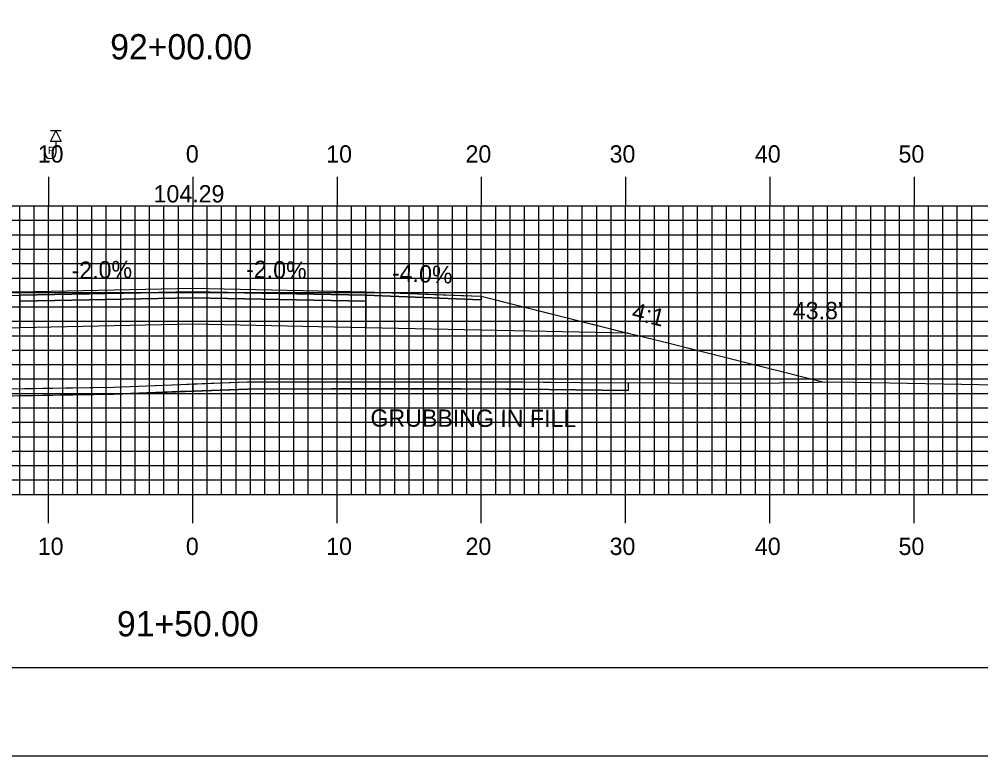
# Model space of a CAD drawing. Extents: x 1764939 to 1765282, y 442591 to 442811.
# Drawn here: x 1765092.8 to 1765159.5, y 442590.5 to 442641.6 of the extents above; entities that cross this region are included whole.
import ezdxf

# ---------------------------------------------------------------- set-up
doc = ezdxf.new("R2010")
doc.units = 0
for name, color, linetype in [('ANNOTATION', 7, 'Continuous'), ('BORDER', 7, 'Continuous'), ('D_Roadway_Centerline', 7, 'Continuous'), ('D_Roadway_Centerline_Text', 7, 'Continuous'), ('D_Roadway_Edge_Shoulder', 7, 'Continuous'), ('D_Roadway_Edge_TW', 7, 'Continuous'), ('D_Roadway_Pavement', 7, 'Continuous'), ('D_Roadway_SlopeLines', 7, 'Continuous'), ('D_Roadway_SubGrade', 7, 'Continuous'), ('D_Text_Standard', 7, 'Continuous'), ('GRUBBING IN FILL', 7, 'Continuous'), ('H_V ANNOTATION', 7, 'Continuous'), ('MAJOR', 7, 'Continuous'), ('MINOR', 7, 'Continuous'), ('PLOT BOUNDARY', 7, 'Continuous'), ('ROCKS', 7, 'Continuous'), ('S_Roadway_Centerline', 7, 'Continuous')]:
    doc.layers.add(name, color=color, linetype=linetype)

msp = doc.modelspace()

# ---------------------------------------------------------------- linework, layer by layer
at = {"layer": 'BORDER'}
msp.add_lwpolyline([(1764955.258, 442596.665), (1765275.258, 442596.665), (1765275.258, 442806.665), (1764955.258, 442806.665)], close=True, dxfattribs=at)
at = {"layer": 'D_Roadway_Centerline'}
msp.add_lwpolyline([(1765056.16, 442615.221), (1765056.164, 442615.222), (1765074.684, 442619.852), (1765074.686, 442619.853), (1765079.216, 442620.986), (1765084.858, 442622.396), (1765084.861, 442622.396), (1765088.541, 442622.544), (1765092.858, 442622.716), (1765092.862, 442622.716), (1765104.858, 442622.956), (1765104.863, 442622.956), (1765116.858, 442622.716), (1765116.862, 442622.716), (1765122.811, 442622.478), (1765124.857, 442622.396), (1765124.858, 442622.396), (1765135.028, 442619.853), (1765135.032, 442619.852), (1765136.858, 442619.396), (1765136.86, 442619.396), (1765148.626, 442616.453)], dxfattribs=at)
at = {"layer": 'D_Roadway_Edge_Shoulder'}
for points in [[(1765092.858, 442622.716), (1765084.858, 442622.396), (1765084.858, 442622.146), (1765092.858, 442622.466)], [(1765116.858, 442622.716), (1765124.858, 442622.396), (1765124.858, 442622.146), (1765116.858, 442622.466)]]:
    msp.add_lwpolyline(points, close=True, dxfattribs=at)
at = {"layer": 'D_Roadway_Edge_TW'}
for points in [[(1765092.858, 442622.466), (1765092.858, 442622.716), (1765104.858, 442622.956), (1765116.858, 442622.716), (1765116.858, 442622.466), (1765104.858, 442622.706)], [(1765116.858, 442622.716), (1765116.858, 442622.716), (1765116.858, 442622.466), (1765116.858, 442622.466)]]:
    msp.add_lwpolyline(points, close=True, dxfattribs=at)
at = {"layer": 'D_Roadway_Pavement'}
for points in [[(1765092.858, 442622.049), (1765092.858, 442622.466), (1765104.858, 442622.706), (1765116.858, 442622.466), (1765116.858, 442622.049), (1765104.858, 442622.289)], [(1765116.858, 442622.466), (1765116.858, 442622.466), (1765116.858, 442622.049), (1765116.858, 442622.049)]]:
    msp.add_lwpolyline(points, close=True, dxfattribs=at)
msp.add_lwpolyline([(1765116.858, 442622.466), (1765116.858, 442622.049)], dxfattribs=at)
msp.add_lwpolyline([(1765116.858, 442622.466), (1765116.858, 442622.049)], dxfattribs=at)
msp.add_lwpolyline([(1765116.858, 442622.466), (1765116.858, 442622.049)], dxfattribs=at)
at = {"layer": 'D_Roadway_SlopeLines'}
msp.add_lwpolyline([(1765124.858, 442622.396), (1765135.032, 442619.852), (1765136.858, 442619.396), (1765148.626, 442616.453)], dxfattribs=at)
at = {"layer": 'D_Roadway_SubGrade'}
for points in [[(1765084.858, 442622.146), (1765092.858, 442622.466), (1765092.858, 442622.049), (1765092.858, 442620.216), (1765074.684, 442619.852), (1765084.858, 442622.396)], [(1765092.858, 442620.216), (1765092.858, 442622.049), (1765104.858, 442622.289), (1765116.858, 442622.049), (1765116.858, 442620.216), (1765104.858, 442620.456)], [(1765116.858, 442622.049), (1765116.858, 442622.466), (1765124.858, 442622.146), (1765124.858, 442622.396), (1765135.032, 442619.852), (1765116.858, 442620.216)], [(1765116.858, 442622.049), (1765116.858, 442622.049), (1765116.858, 442620.216), (1765116.858, 442620.216)]]:
    msp.add_lwpolyline(points, close=True, dxfattribs=at)
at = {"layer": 'GRUBBING IN FILL'}
msp.add_line((1765135.032, 442616.409), (1765135.032, 442615.878), dxfattribs=at)
for points in [[(1765074.684, 442615.226), (1765079.043, 442615.431), (1765084.267, 442615.687), (1765089.492, 442615.943), (1765094.426, 442616.025), (1765099.361, 442616.107), (1765103.995, 442616.288), (1765104.858, 442616.322), (1765104.858, 442615.822), (1765104.007, 442615.788), (1765099.375, 442615.607), (1765094.442, 442615.525), (1765089.508, 442615.443), (1765084.287, 442615.187), (1765079.067, 442614.931), (1765074.684, 442614.725)], [(1765074.684, 442615.226), (1765079.043, 442615.431), (1765084.267, 442615.687), (1765089.492, 442615.943), (1765094.426, 442616.025), (1765099.361, 442616.107), (1765103.995, 442616.288), (1765104.858, 442616.322), (1765104.858, 442615.822), (1765104.007, 442615.788), (1765099.375, 442615.607), (1765094.442, 442615.525), (1765089.508, 442615.443), (1765084.287, 442615.187), (1765079.067, 442614.931), (1765074.684, 442614.725)], [(1765104.858, 442616.322), (1765108.63, 442616.47), (1765114.476, 442616.473), (1765120.322, 442616.477), (1765123.457, 442616.473), (1765126.593, 442616.47), (1765131.711, 442616.42), (1765135.032, 442616.409), (1765135.032, 442615.878), (1765131.372, 442615.925), (1765127.712, 442615.971), (1765123.457, 442615.973), (1765114.481, 442615.973), (1765108.64, 442615.97), (1765104.858, 442615.822)], [(1765104.858, 442616.322), (1765108.63, 442616.47), (1765114.476, 442616.473), (1765120.322, 442616.477), (1765123.457, 442616.473), (1765126.593, 442616.47), (1765131.711, 442616.42), (1765135.032, 442616.409), (1765135.032, 442615.878), (1765131.372, 442615.925), (1765127.712, 442615.971), (1765123.457, 442615.973), (1765114.481, 442615.973), (1765108.64, 442615.97), (1765104.858, 442615.822)]]:
    msp.add_lwpolyline(points, close=True, dxfattribs=at)
msp.add_lwpolyline([(1765074.684, 442614.725), (1765079.067, 442614.931), (1765089.508, 442615.443), (1765099.375, 442615.607), (1765108.64, 442615.97), (1765120.322, 442615.977), (1765126.592, 442615.97), (1765127.712, 442615.971), (1765135.032, 442615.878)], dxfattribs=at)
at = {"layer": 'MAJOR'}
for p, q in [((1765094.858, 442630.669), (1765094.858, 442628.665)), ((1765104.858, 442630.669), (1765104.858, 442628.665)), ((1765114.858, 442630.669), (1765114.858, 442628.665)), ((1765124.858, 442630.669), (1765124.858, 442628.665)), ((1765134.858, 442630.669), (1765134.858, 442628.665)), ((1765144.858, 442630.669), (1765144.858, 442628.665)), ((1765154.858, 442630.669), (1765154.858, 442628.665)), ((1764964.858, 442628.665), (1765244.858, 442628.665)), ((1764964.858, 442628.665), (1765244.858, 442628.665)), ((1765094.858, 442608.665), (1765094.858, 442628.665)), ((1765104.858, 442608.665), (1765104.858, 442628.665)), ((1765114.858, 442608.665), (1765114.858, 442628.665)), ((1765124.858, 442608.665), (1765124.858, 442628.665)), ((1765134.858, 442608.665), (1765134.858, 442628.665)), ((1765144.858, 442608.665), (1765144.858, 442628.665)), ((1765154.858, 442608.665), (1765154.858, 442628.665)), ((1764964.858, 442623.665), (1765244.858, 442623.665)), ((1764964.858, 442618.665), (1765244.858, 442618.665)), ((1764964.858, 442613.665), (1765244.858, 442613.665)), ((1764964.858, 442608.665), (1765244.858, 442608.665)), ((1764964.858, 442608.665), (1765244.858, 442608.665)), ((1765094.858, 442606.661), (1765094.858, 442608.665)), ((1765104.858, 442606.661), (1765104.858, 442608.665)), ((1765114.858, 442606.661), (1765114.858, 442608.665)), ((1765124.858, 442606.661), (1765124.858, 442608.665)), ((1765134.858, 442606.661), (1765134.858, 442608.665)), ((1765144.858, 442606.661), (1765144.858, 442608.665)), ((1765154.858, 442606.661), (1765154.858, 442608.665))]:
    msp.add_line(p, q, dxfattribs=at)
at = {"layer": 'MINOR'}
for p, q in [((1765092.858, 442608.665), (1765092.858, 442628.665)), ((1765093.858, 442608.665), (1765093.858, 442628.665)), ((1765095.858, 442608.665), (1765095.858, 442628.665)), ((1765096.858, 442608.665), (1765096.858, 442628.665)), ((1765097.858, 442608.665), (1765097.858, 442628.665)), ((1765098.858, 442608.665), (1765098.858, 442628.665)), ((1765099.858, 442608.665), (1765099.858, 442628.665)), ((1765100.858, 442608.665), (1765100.858, 442628.665)), ((1765101.858, 442608.665), (1765101.858, 442628.665)), ((1765102.858, 442608.665), (1765102.858, 442628.665)), ((1765103.858, 442608.665), (1765103.858, 442628.665)), ((1765105.858, 442608.665), (1765105.858, 442628.665)), ((1765106.858, 442608.665), (1765106.858, 442628.665)), ((1765107.858, 442608.665), (1765107.858, 442628.665)), ((1765108.858, 442608.665), (1765108.858, 442628.665)), ((1765109.858, 442608.665), (1765109.858, 442628.665)), ((1765110.858, 442608.665), (1765110.858, 442628.665)), ((1765111.858, 442608.665), (1765111.858, 442628.665)), ((1765112.858, 442608.665), (1765112.858, 442628.665)), ((1765113.858, 442608.665), (1765113.858, 442628.665)), ((1765115.858, 442608.665), (1765115.858, 442628.665)), ((1765116.858, 442608.665), (1765116.858, 442628.665)), ((1765117.858, 442608.665), (1765117.858, 442628.665)), ((1765118.858, 442608.665), (1765118.858, 442628.665)), ((1765119.858, 442608.665), (1765119.858, 442628.665)), ((1765120.858, 442608.665), (1765120.858, 442628.665)), ((1765121.858, 442608.665), (1765121.858, 442628.665)), ((1765122.858, 442608.665), (1765122.858, 442628.665)), ((1765123.858, 442608.665), (1765123.858, 442628.665)), ((1765125.858, 442608.665), (1765125.858, 442628.665)), ((1765126.858, 442608.665), (1765126.858, 442628.665)), ((1765127.858, 442608.665), (1765127.858, 442628.665)), ((1765128.858, 442608.665), (1765128.858, 442628.665)), ((1765129.858, 442608.665), (1765129.858, 442628.665)), ((1765130.858, 442608.665), (1765130.858, 442628.665)), ((1765131.858, 442608.665), (1765131.858, 442628.665)), ((1765132.858, 442608.665), (1765132.858, 442628.665)), ((1765133.858, 442608.665), (1765133.858, 442628.665)), ((1765135.858, 442608.665), (1765135.858, 442628.665)), ((1765136.858, 442608.665), (1765136.858, 442628.665)), ((1765137.858, 442608.665), (1765137.858, 442628.665)), ((1765138.858, 442608.665), (1765138.858, 442628.665)), ((1765139.858, 442608.665), (1765139.858, 442628.665)), ((1765140.858, 442608.665), (1765140.858, 442628.665)), ((1765141.858, 442608.665), (1765141.858, 442628.665)), ((1765142.858, 442608.665), (1765142.858, 442628.665)), ((1765143.858, 442608.665), (1765143.858, 442628.665)), ((1765145.858, 442608.665), (1765145.858, 442628.665)), ((1765146.858, 442608.665), (1765146.858, 442628.665)), ((1765147.858, 442608.665), (1765147.858, 442628.665)), ((1765148.858, 442608.665), (1765148.858, 442628.665)), ((1765149.858, 442608.665), (1765149.858, 442628.665)), ((1765150.858, 442608.665), (1765150.858, 442628.665)), ((1765151.858, 442608.665), (1765151.858, 442628.665)), ((1765152.858, 442608.665), (1765152.858, 442628.665)), ((1765153.858, 442608.665), (1765153.858, 442628.665)), ((1765155.858, 442608.665), (1765155.858, 442628.665)), ((1765156.858, 442608.665), (1765156.858, 442628.665)), ((1765157.858, 442608.665), (1765157.858, 442628.665)), ((1765158.858, 442608.665), (1765158.858, 442628.665)), ((1764964.858, 442627.665), (1765244.858, 442627.665)), ((1764964.858, 442626.665), (1765244.858, 442626.665)), ((1764964.858, 442625.665), (1765244.858, 442625.665)), ((1764964.858, 442624.665), (1765244.858, 442624.665)), ((1764964.858, 442622.665), (1765244.858, 442622.665)), ((1764964.858, 442621.665), (1765244.858, 442621.665)), ((1764964.858, 442620.665), (1765244.858, 442620.665)), ((1764964.858, 442619.665), (1765244.858, 442619.665)), ((1764964.858, 442617.665), (1765244.858, 442617.665)), ((1764964.858, 442616.665), (1765244.858, 442616.665)), ((1764964.858, 442615.665), (1765244.858, 442615.665)), ((1764964.858, 442614.665), (1765244.858, 442614.665)), ((1764964.858, 442612.665), (1765244.858, 442612.665)), ((1764964.858, 442611.665), (1765244.858, 442611.665)), ((1764964.858, 442610.665), (1765244.858, 442610.665)), ((1764964.858, 442609.665), (1765244.858, 442609.665))]:
    msp.add_line(p, q, dxfattribs=at)
at = {"layer": 'PLOT BOUNDARY'}
msp.add_lwpolyline([(1764939.071, 442590.547), (1765279.071, 442590.547), (1765279.071, 442810.547), (1764939.071, 442810.547)], close=True, dxfattribs=at)
at = {"layer": 'ROCKS'}
for p, q in [((1765095.727, 442633.865), (1765094.989, 442633.865)), ((1765095.358, 442633.127), (1765095.358, 442632.312))]:
    msp.add_line(p, q, dxfattribs=at)
msp.add_lwpolyline([(1765095.358, 442633.865), (1765095.727, 442633.127), (1765094.989, 442633.127)], close=True, dxfattribs=at)
msp.add_arc((1765094.985, 442632.312), 0.373, 180, 0, dxfattribs=at)
at = {"layer": 'S_Roadway_Centerline'}
msp.add_lwpolyline([(1765038.724, 442615.255), (1765055.02, 442615.243), (1765062.981, 442615.091), (1765063.048, 442615.09), (1765063.43, 442615.088), (1765070.994, 442615.054), (1765073.235, 442615.157), (1765079.043, 442615.431), (1765089.492, 442615.943), (1765099.361, 442616.107), (1765108.63, 442616.47), (1765120.322, 442616.477), (1765126.593, 442616.47), (1765127.715, 442616.471), (1765131.711, 442616.42), (1765144.246, 442616.379), (1765149.43, 442616.467), (1765161.878, 442616.234)], dxfattribs=at)

# ---------------------------------------------------------------- texts
at = {"layer": 'ANNOTATION'}
for s, rotation, p in [('-2.0%', 1.14571, (1765096.466, 442623.589)), ('-2.0%', 358.85423, (1765108.547, 442623.683)), ('-4.0%', 357.70929, (1765118.651, 442623.446)), ('4:1', 345.96053, (1765135.217, 442620.821))]:
    msp.add_text(s, height=1.2, rotation=rotation, dxfattribs=at).set_placement(p)
at = {"layer": 'D_Roadway_Centerline'}
for s, p in [('C', (1765104.853, 442622.956)), ('L', (1765104.858, 442622.949))]:
    msp.add_text(s, height=0.0146, dxfattribs=at).set_placement(p)
at = {"layer": 'D_Roadway_Centerline_Text'}
msp.add_text('104.29', height=1.2, dxfattribs=at).set_placement((1765102.14, 442628.903))
at = {"layer": 'D_Text_Standard'}
msp.add_text("43.8'", height=1.2, dxfattribs=at).set_placement((1765146.458, 442620.81))
at = {"layer": 'GRUBBING IN FILL'}
msp.add_text('GRUBBING IN FILL', height=1.2, rotation=359.86728, dxfattribs=at).set_placement((1765117.173, 442613.363))
at = {"layer": 'H_V ANNOTATION'}
for s, height, p in [('92+00.00', 1.75, (1765099.13, 442638.821)), ('10', 1.2, (1765094.109, 442631.665)), ('0', 1.2, (1765104.376, 442631.665)), ('10', 1.2, (1765114.109, 442631.665)), ('20', 1.2, (1765123.766, 442631.665)), ('30', 1.2, (1765133.755, 442631.665)), ('40', 1.2, (1765143.83, 442631.665)), ('50', 1.2, (1765153.787, 442631.665)), ('10', 1.2, (1765094.109, 442604.465)), ('0', 1.2, (1765104.376, 442604.465)), ('10', 1.2, (1765114.109, 442604.465)), ('20', 1.2, (1765123.766, 442604.465)), ('30', 1.2, (1765133.755, 442604.465)), ('40', 1.2, (1765143.83, 442604.465)), ('50', 1.2, (1765153.787, 442604.465)), ('91+50.00', 1.75, (1765099.599, 442598.821))]:
    msp.add_text(s, height=height, dxfattribs=at).set_placement(p)
at = {"layer": 'ROCKS'}
msp.add_text('R', height=0.492, dxfattribs=at).set_placement((1765094.813, 442632.27))

doc.saveas('drawing.dxf')
